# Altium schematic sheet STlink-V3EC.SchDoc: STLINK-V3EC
size A3; Date: Not used; ApprovedBy: Not used; CheckedBy: Not used; Author: Not used; CompanyName: STMicroelectronics; DrawnBy: Not used; Engineer: Not used; Organization: Not used; Address1: Not used; Address2: Not used; Address3: Not used; Address4: Not used; DocumentNumber: Not used; Revision: Not used; SheetNumber: 6; SheetTotal: 7
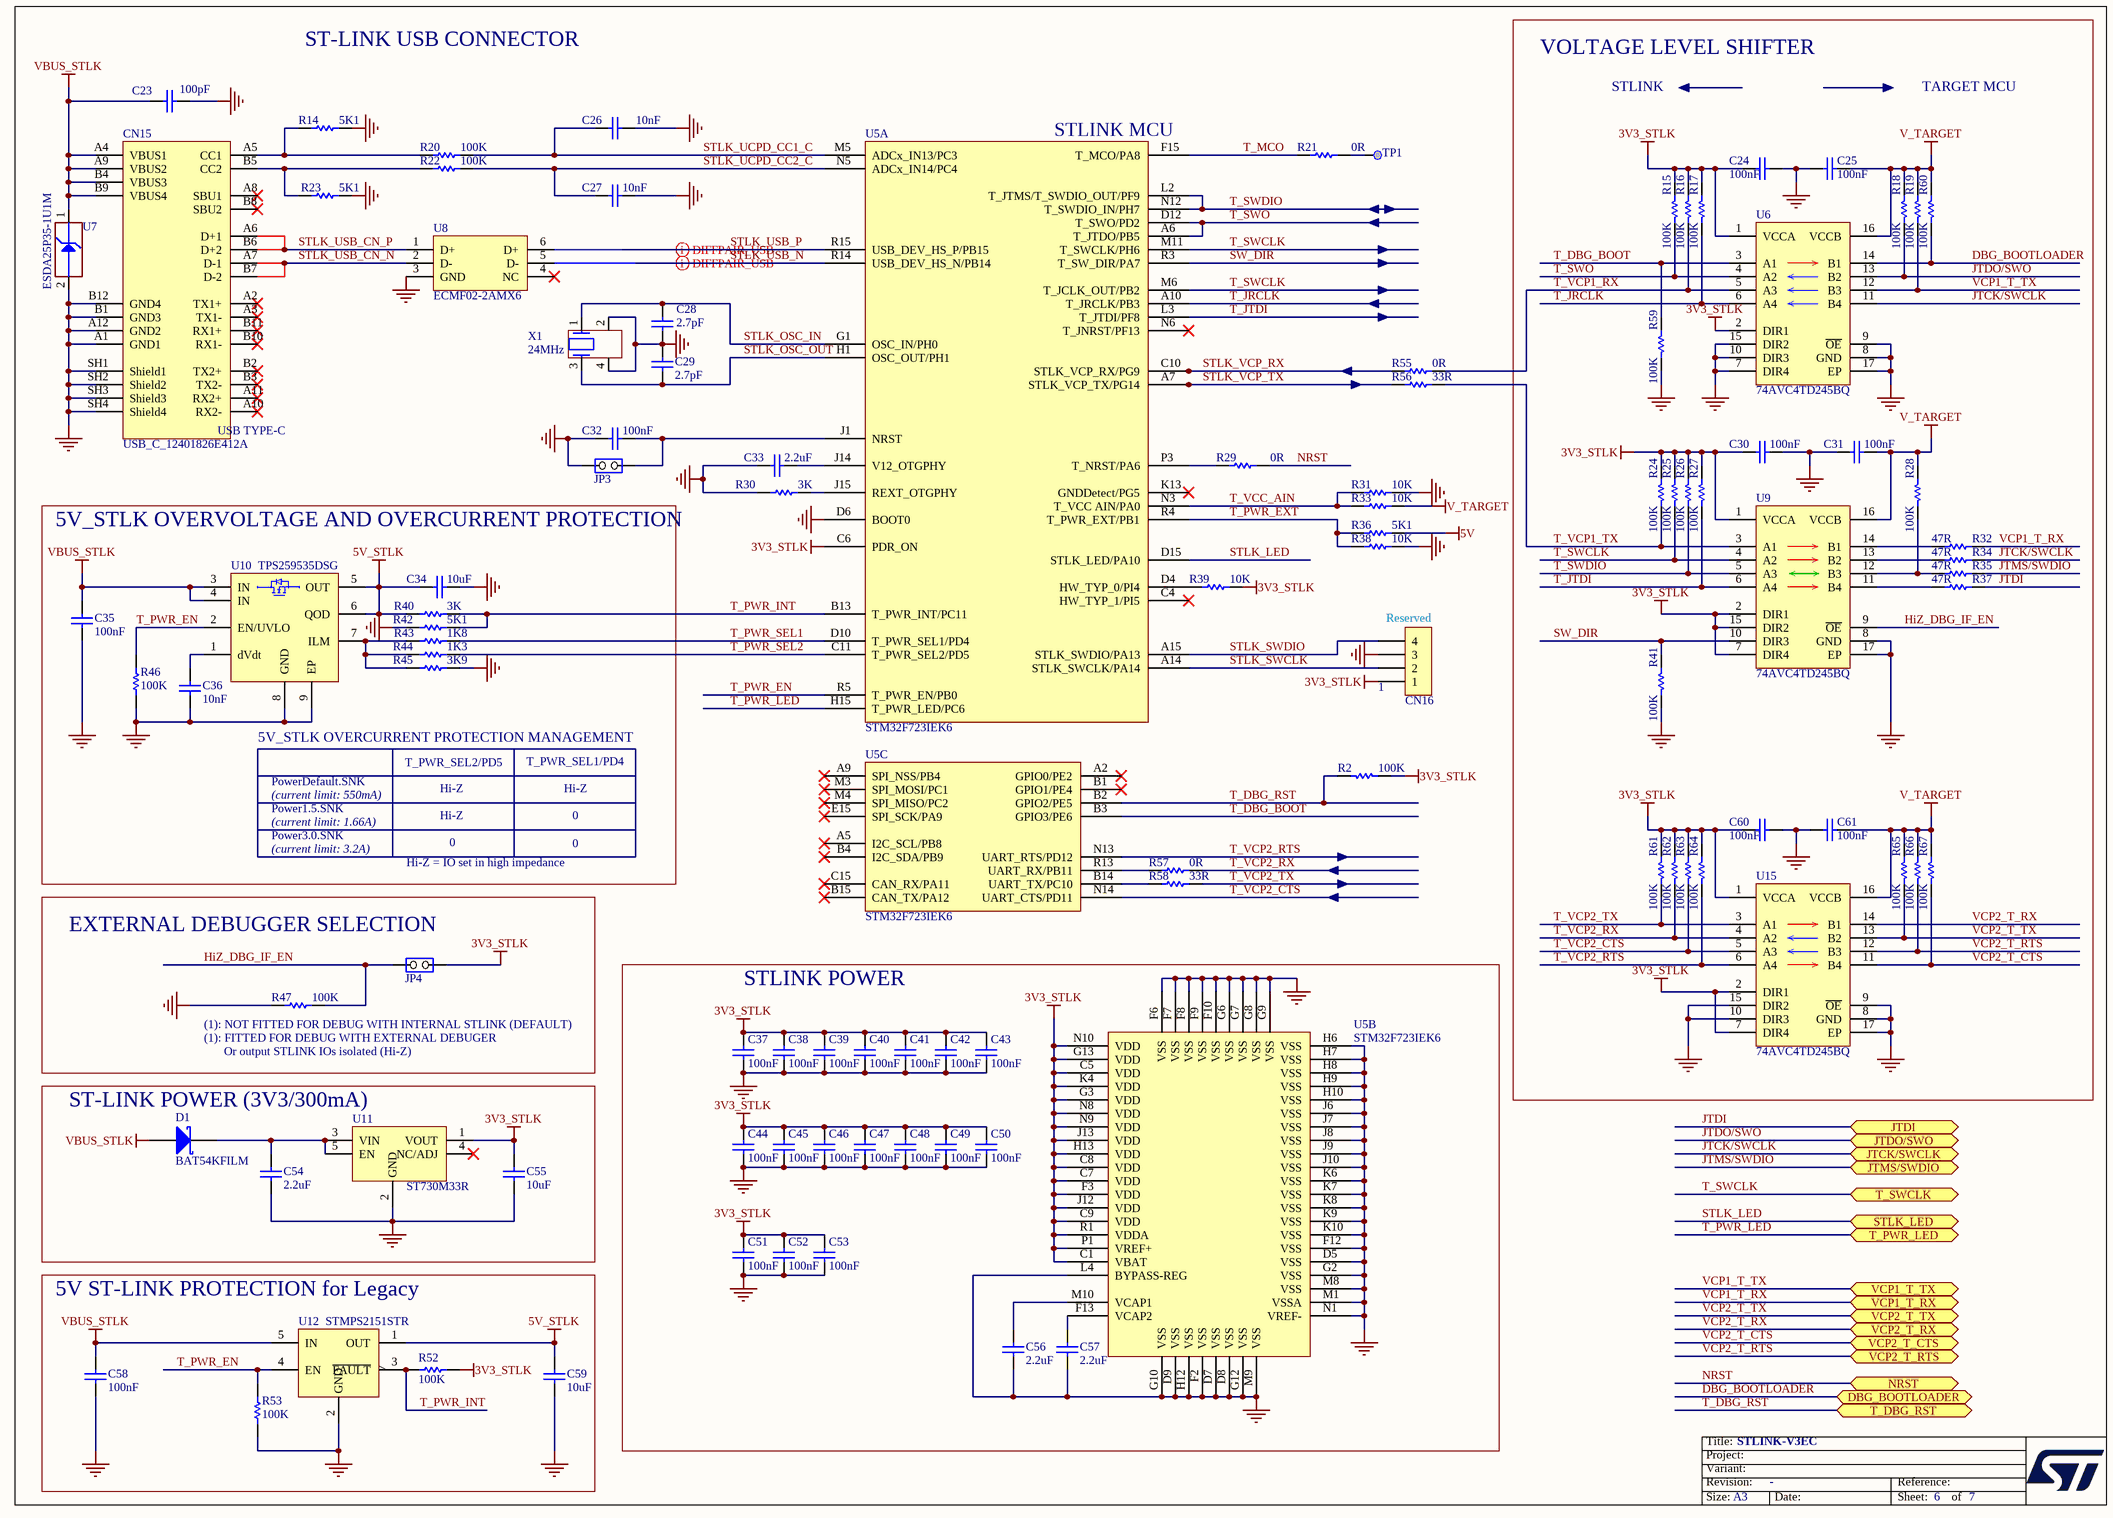
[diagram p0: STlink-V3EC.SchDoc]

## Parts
C23  value 100pF  [C0402]  (hidden comment: Capacitor)
C24  value 100nF  [C0402]  (hidden comment: Capacitor)
C25  value 100nF  [C0402]  (hidden comment: Capacitor)
C26  value 10nF  [C0402]  (hidden comment: Capacitor)
C27  value 10nF  [C0402]  (hidden comment: Capacitor)
C28  value 2.7pF  [C0402]  (hidden comment: Capacitor)
C29  value 2.7pF  [C0402]  (hidden comment: Capacitor)
C30  value 100nF  [C0402]  (hidden comment: Capacitor)
C31  value 100nF  [C0402]  (hidden comment: Capacitor)
C32  value 100nF  [C0402]  (hidden comment: Capacitor)
C33  value 2.2uF  [C0402]  (hidden comment: Capacitor)
C34  value 10uF  [C0603]  (hidden comment: Capacitor)
C35  value 100nF  [C0402]  (hidden comment: Capacitor)
C36  value 10nF  [C0402]  (hidden comment: Capacitor)
C37  value 100nF  [C0402]  (hidden comment: Capacitor)
C38  value 100nF  [C0402]  (hidden comment: Capacitor)
C39  value 100nF  [C0402]  (hidden comment: Capacitor)
C40  value 100nF  [C0402]  (hidden comment: Capacitor)
C41  value 100nF  [C0402]  (hidden comment: Capacitor)
C42  value 100nF  [C0402]  (hidden comment: Capacitor)
C43  value 100nF  [C0402]  (hidden comment: Capacitor)
C44  value 100nF  [C0402]  (hidden comment: Capacitor)
C45  value 100nF  [C0402]  (hidden comment: Capacitor)
C46  value 100nF  [C0402]  (hidden comment: Capacitor)
C47  value 100nF  [C0402]  (hidden comment: Capacitor)
C48  value 100nF  [C0402]  (hidden comment: Capacitor)
C49  value 100nF  [C0402]  (hidden comment: Capacitor)
C50  value 100nF  [C0402]  (hidden comment: Capacitor)
C51  value 100nF  [C0402]  (hidden comment: Capacitor)
C52  value 100nF  [C0402]  (hidden comment: Capacitor)
C53  value 100nF  [C0402]  (hidden comment: Capacitor)
C54  value 2.2uF  [C0805]  (hidden comment: Capacitor)
C55  value 10uF  [C0603]  (hidden comment: Capacitor)
C56  value 2.2uF  [C0402]  (hidden comment: Capacitor)
C57  value 2.2uF  [C0402]  (hidden comment: Capacitor)
C58  value 100nF  [C0402]  (hidden comment: Capacitor)
C59  value 10uF  [C0603]  (hidden comment: Capacitor)
C60  value 100nF  [C0402]  (hidden comment: Capacitor)
C61  value 100nF  [C0402]  (hidden comment: Capacitor)
CN15  value USB_C_12401826E412A  [CON_USB-TYPEC_AMPHENOL_12401826E412A]  (hidden comment: USB_TYPE_C_Receptacle)
CN16  Header 4x1  [CON_SAMTEC_TSW-104-07-G-S]  (value not drawn)
D1  value BAT54KFILM  [DIO_SOD523_1A_2K]  (hidden comment: SCHOTTKY_1A_2K)
JP3  Jumper_Header 2x1  [CON_SAMTEC_TSW-102-07-G-S]  (value not drawn)
JP4  Jumper_Header 2x1  [CON_SAMTEC_TSW-102-07-G-S]  (value not drawn)
R2  value 100K  [R0402]  (hidden comment: Resistor)
R14  value 5K1  [R0402]  (hidden comment: Resistor)
R15  value 100K  [R0402]  (hidden comment: Resistor)
R16  value 100K  [R0402]  (hidden comment: Resistor)
R17  value 100K  [R0402]  (hidden comment: Resistor)
R18  value 100K  [R0402]  (hidden comment: Resistor)
R19  value 100K  [R0402]  (hidden comment: Resistor)
R20  value 100K  [R0402]  (hidden comment: Resistor)
R21  value 0R  [R0402]  (hidden comment: Resistor)
R22  value 100K  [R0402]  (hidden comment: Resistor)
R23  value 5K1  [R0402]  (hidden comment: Resistor)
R24  value 100K  [R0402]  (hidden comment: Resistor)
R25  value 100K  [R0402]  (hidden comment: Resistor)
R26  value 100K  [R0402]  (hidden comment: Resistor)
R27  value 100K  [R0402]  (hidden comment: Resistor)
R28  value 100K  [R0402]  (hidden comment: Resistor)
R29  value 0R  [R0402]  (hidden comment: Resistor)
R30  value 3K  [R0402]  (hidden comment: Resistor)
R31  value 10K  [R0402]  (hidden comment: Resistor)
R32  value 47R  [R0402]  (hidden comment: Resistor)
R33  value 10K  [R0402]  (hidden comment: Resistor)
R34  value 47R  [R0402]  (hidden comment: Resistor)
R35  value 47R  [R0402]  (hidden comment: Resistor)
R36  value 5K1  [R0402]  (hidden comment: Resistor)
R37  value 47R  [R0402]  (hidden comment: Resistor)
R38  value 10K  [R0402]  (hidden comment: Resistor)
R39  value 10K  [R0402]  (hidden comment: Resistor)
R40  value 3K  [R0402]  (hidden comment: Resistor)
R41  value 100K  [R0402]  (hidden comment: Resistor)
R42  value 5K1  [R0402]  (hidden comment: Resistor)
R43  value 1K8  [R0402]  (hidden comment: Resistor)
R44  value 1K3  [R0402]  (hidden comment: Resistor)
R45  value 3K9  [R0402]  (hidden comment: Resistor)
R46  value 100K  [R0402]  (hidden comment: Resistor)
R47  value 100K  [R0402]  (hidden comment: Resistor)
R52  value 100K  [R0402]  (hidden comment: Resistor)
R53  value 100K  [R0402]  (hidden comment: Resistor)
R55  value 0R  [R0402]  (hidden comment: Resistor)
R56  value 33R  [R0402]  (hidden comment: Resistor)
R57  value 0R  [R0402]  (hidden comment: Resistor)
R58  value 33R  [R0402]  (hidden comment: Resistor)
R59  value 100K  [R0402]  (hidden comment: Resistor)
R60  value 100K  [R0402]  (hidden comment: Resistor)
R61  value 100K  [R0402]  (hidden comment: Resistor)
R62  value 100K  [R0402]  (hidden comment: Resistor)
R63  value 100K  [R0402]  (hidden comment: Resistor)
R64  value 100K  [R0402]  (hidden comment: Resistor)
R65  value 100K  [R0402]  (hidden comment: Resistor)
R66  value 100K  [R0402]  (hidden comment: Resistor)
R67  value 100K  [R0402]  (hidden comment: Resistor)
TP1  Test Point  [TP_SMD_1MM]  (value not drawn)  (no BOM)
U5  value STM32F723IEK6  [ICC_UFBGA201_176+25_10X10_P065]  (hidden comment: STLINK-V3EC_Old)  (parts A,B,C of 3)
U6  74AVC4TD245BQ  [ICC_DHVQFN16-EPAD_SOT763-1_2P5X3P5_H0P85_P050]
U7  value ESDA25P35-1U1M  [ESD_QFN1610_2N_1K_2A]  (hidden comment: ESD-TRANSIL)
U8  ECMF02-2AMX6  [ESD_QFN-6L_1P7X1P5_P050]
U9  74AVC4TD245BQ  [ICC_DHVQFN16-EPAD_SOT763-1_2P5X3P5_H0P85_P050]
U10  TPS259535DSG  [ICC_WSON8-EPAD_2X2_P050]
U11  ST730M33R  [ICC_SOT23-5L_H1P45]
U12  STMPS2151STR  [MOS_SOT23-5L]
U15  74AVC4TD245BQ  [ICC_DHVQFN16-EPAD_SOT763-1_2P5X3P5_H0P85_P050]
X1  value 24MHz  [CRY_NX2016SA_4P]  (hidden comment: XTAL_4_PINS)

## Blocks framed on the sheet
VOLTAGE LEVEL SHIFTER: C24 C25 C30 C31 C60 C61 R15-R19 R24-R28 R32 R34 R35 R37 R41 R59-R67 U6 U9 U15
5V_STLK OVERVOLTAGE AND OVERCURRENT PROTECTION: C34-C36 R40 R42-R46 U10
EXTERNAL DEBUGGER SELECTION: JP4 R47
STLINK POWER: C37-C53 C56 C57 U5
ST-LINK POWER (3V3/300mA): C54 C55 D1 U11
5V ST-LINK PROTECTION for Legacy: C58 C59 R52 R53 U12

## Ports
DBG_BOOTLOADER (bidir), JTCK/SWCLK (bidir), JTDI (bidir), JTDO/SWO (bidir), JTMS/SWDIO (bidir), NRST (bidir), STLK_LED (bidir), T_DBG_RST (bidir), T_PWR_LED (bidir), T_SWCLK (bidir), VCP1_T_RX (bidir), VCP1_T_TX (bidir), VCP2_T_CTS (bidir), VCP2_T_RTS (bidir), VCP2_T_RX (bidir), VCP2_T_TX (bidir)

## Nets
3V3_STLK: C24.2 C30.2 C37.1 C38.1 C39.1 C40.1 C41.1 C42.1 C43.1 C44.1 C45.1 C46.1 C47.1 C48.1 C49.1 C50.1 C51.1 C52.1 C53.1 C55.2 C60.2 CN16.1 JP4.1(COMMON) R2.1 R15.2 R16.2 R17.2 R24.1 R25.2 R26.2 R27.2 R39.2 R52.1 R61.2 R62.2 R63.2 R64.2 U5.C1(VBAT) U5.C5(VDD) U5.C6(PDR_ON) U5.C7(VDD) U5.C8(VDD) U5.C9(VDD) U5.F3(VDD) U5.G3(VDD) U5.G13(VDD) U5.H13(VDD) U5.J12(VDD) U5.J13(VDD) U5.K4(VDD) U5.N8(VDD) U5.N9(VDD) U5.N10(VDD) U5.P1(VREF+) U5.R1(VDDA) U6.1(VCCA) U6.2(DIR1) U9.1(VCCA) U9.2(DIR1) U9.7(DIR4) U9.15(DIR2) U11.1(VOUT) U15.1(VCCA) U15.2(DIR1) U15.7(DIR4)
5V: R36.2
5V_STLK: C34.2 C59.2 R40.1 U10.5(OUT) U10.6(QOD) U12.1(OUT)
GND: C23.2 C24.1 C25.2 C26.2 C27.2 C28.1 C29.2 C30.1 C31.2 C32.1 C33.1 C34.1 C35.1 C36.1 C37.2 C38.2 C39.2 C40.2 C41.2 C42.2 C43.2 C44.2 C45.2 C46.2 C47.2 C48.2 C49.2 C50.2 C51.2 C52.2 C53.2 C54.1 C55.1 C56.1 C57.1 C58.1 C59.1 C60.1 C61.2 CN15.A1(GND1) CN15.A12(GND2) CN15.B1(GND3) CN15.B12(GND4) CN15.SH1(Shield1) CN15.SH2(Shield2) CN15.SH3(Shield3) CN15.SH4(Shield4) CN16.3 JP3.2(NO) R14.2 R23.2 R30.2 R31.2 R38.2 R41.1 R42.1 R45.2 R46.1 R47.1 R53.1 R59.1 U5.D5(VSS) U5.D6(BOOT0) U5.D7(VSS) U5.D8(VSS) U5.D9(VSS) U5.F2(VSS) U5.F6(VSS) U5.F7(VSS) U5.F8(VSS) U5.F9(VSS) U5.F10(VSS) U5.F12(VSS) U5.G2(VSS) U5.G6(VSS) U5.G7(VSS) U5.G8(VSS) U5.G9(VSS) U5.G10(VSS) U5.G12(VSS) U5.H6(VSS) U5.H7(VSS) U5.H8(VSS) U5.H9(VSS) U5.H10(VSS) U5.H12(VSS) U5.J6(VSS) U5.J7(VSS) U5.J8(VSS) U5.J9(VSS) U5.J10(VSS) U5.K6(VSS) U5.K7(VSS) U5.K8(VSS) U5.K9(VSS) U5.K10(VSS) U5.L4(BYPASS-REG) U5.M1(VSSA) U5.M8(VSS) U5.M9(VSS) U5.N1(VREF-) U6.7(DIR4) U6.8(GND) U6.9(~{OE}) U6.10(DIR3) U6.15(DIR2) U6.17(EP) U7.2(GND) U8.3(GND) U9.8(GND) U9.17(EP) U10.8(GND) U10.9(EP) U11.2(GND) U12.2(GND) U15.8(GND) U15.9(~{OE}) U15.10(DIR3) U15.15(DIR2) U15.17(EP) X1.2 X1.4
V_TARGET: C25.1 C31.1 C61.1 R18.2 R19.2 R28.2 R33.2 R60.2 R65.2 R66.2 R67.2 U6.16(VCCB) U9.16(VCCB) U15.16(VCCB)
VBUS_STLK: C23.1 C35.2 C58.2 CN15.A4(VBUS1) CN15.A9(VBUS2) CN15.B4(VBUS3) CN15.B9(VBUS4) D1.1(A) U7.1(IO1) U10.3(IN) U10.4(IN) U12.5(IN)
DBG_BOOTLOADER: R60.1 U6.14(B1) ; port DBG_BOOTLOADER
HiZ_DBG_IF_EN: JP4.2(NO) R47.2 U9.9(~{OE})
JTCK/SWCLK: R34.2 U6.11(B4) ; port JTCK/SWCLK
JTDI: R37.2 ; port JTDI
JTDO/SWO: R18.1 U6.13(B2) ; port JTDO/SWO
JTMS/SWDIO: R35.2 ; port JTMS/SWDIO
NRST: R29.2 ; port NRST
STLK_LED: U5.D15(STLK_LED/PA10) ; port STLK_LED
STLK_OSC_IN: C28.2 U5.G1(OSC_IN/PH0) X1.1
STLK_OSC_OUT: C29.1 U5.H1(OSC_OUT/PH1) X1.3
STLK_SWCLK: CN16.2 U5.A14(STLK_SWCLK/PA14)
STLK_SWDIO: CN16.4 U5.A15(STLK_SWDIO/PA13)
STLK_UCPD_CC1_C: C26.1 R20.2 U5.M5(ADCx_IN13/PC3)
STLK_UCPD_CC2_C: C27.1 R22.2 U5.N5(ADCx_IN14/PC4)
STLK_USB_CN_N: CN15.A7(D-1) CN15.B7(D-2) U8.2(D-)
STLK_USB_CN_P: CN15.A6(D+1) CN15.B6(D+2) U8.1(D+)
STLK_USB_N: U5.R14(USB_DEV_HS_N/PB14) U8.5(D-)
STLK_USB_P: U5.R15(USB_DEV_HS_P/PB15) U8.6(D+)
STLK_VCP_RX: R55.1 U5.C10(STLK_VCP_RX/PG9)
STLK_VCP_TX: R56.1 U5.A7(STLK_VCP_TX/PG14)
SW_DIR: R41.2 U5.R3(T_SW_DIR/PA7) U9.10(DIR3)
T_DBG_BOOT: R59.2 U5.B3(GPIO3/PE6) U6.3(A1)
T_DBG_RST: R2.2 U5.B2(GPIO2/PE5) ; port T_DBG_RST
T_JRCLK: R17.1 U5.A10(T_JRCLK/PB3) U6.6(A4)
T_JTDI: R27.1 U5.L3(T_JTDI/PF8) U9.6(A4)
T_MCO: R21.1 U5.F15(T_MCO/PA8)
T_PWR_EN: R46.2 R53.2 U5.R5(T_PWR_EN/PB0) U10.2(EN/UVLO) U12.4(EN)
T_PWR_EXT: R36.1 R38.1 U5.R4(T_PWR_EXT/PB1)
T_PWR_INT: R40.2 R42.2 R52.2 U5.B13(T_PWR_INT/PC11) U12.3(~{FAULT})
T_PWR_LED: U5.H15(T_PWR_LED/PC6) ; port T_PWR_LED
T_PWR_SEL1: R43.2 U5.D10(T_PWR_SEL1/PD4)
T_PWR_SEL2: R44.2 U5.C11(T_PWR_SEL2/PD5)
T_SWCLK: R25.1 U5.M6(T_JCLK_OUT/PB2) U5.M11(T_SWCLK/PH6) U9.4(A2) ; port T_SWCLK
T_SWDIO: R26.1 U5.L2(T_JTMS/T_SWDIO_OUT/PF9) U5.N12(T_SWDIO_IN/PH7) U9.5(A3)
T_SWO: R15.1 U5.A6(T_JTDO/PB5) U5.D12(T_SWO/PD2) U6.4(A2)
T_VCC_AIN: R31.1 R33.1 U5.N3(T_VCC_AIN/PA0)
T_VCP1_RX: R16.1 R55.2 U6.5(A3)
T_VCP1_TX: R24.2 R56.2 U9.3(A1)
T_VCP2_CTS: R63.1 U5.N14(UART_CTS/PD11) U15.5(A3)
T_VCP2_RTS: R64.1 U5.N13(UART_RTS/PD12) U15.6(A4)
T_VCP2_RX: R57.2 R62.1 U15.4(A2)
T_VCP2_TX: R58.2 R61.1 U15.3(A1)
VCP1_T_RX: R32.2 ; port VCP1_T_RX
VCP1_T_TX: R19.1 U6.12(B3) ; port VCP1_T_TX
VCP2_T_CTS: R67.1 U15.11(B4) ; port VCP2_T_CTS
VCP2_T_RTS: R66.1 U15.12(B3) ; port VCP2_T_RTS
VCP2_T_RX: U15.14(B1) ; port VCP2_T_RX
VCP2_T_TX: R65.1 U15.13(B2) ; port VCP2_T_TX
NetC32_2: C32.2 JP3.1(COMMON) U5.J1(NRST)
NetC33_2: C33.2 U5.J14(V12_OTGPHY)
NetC36_2: C36.2 U10.1(dVdt)
NetC54_2: C54.2 D1.2(K) U11.3(VIN) U11.5(EN)
NetC56_2: C56.2 U5.M10(VCAP1)
NetC57_2: C57.2 U5.F13(VCAP2)
NetCN15_A5: CN15.A5(CC1) R14.1 R20.1
NetCN15_B5: CN15.B5(CC2) R22.1 R23.1
NetR21_2: R21.2 TP1.1
NetR28_1: R28.1 R35.1 U9.12(B3)
NetR29_1: R29.1 U5.P3(T_NRST/PA6)
NetR30_1: R30.1 U5.J15(REXT_OTGPHY)
NetR32_1: R32.1 U9.14(B1)
NetR34_1: R34.1 U9.13(B2)
NetR37_1: R37.1 U9.11(B4)
NetR39_1: R39.1 U5.D4(HW_TYP_0/PI4)
NetR43_1: R43.1 R44.1 R45.1 U10.7(ILM)
NetR57_1: R57.1 U5.R13(UART_RX/PB11)
NetR58_1: R58.1 U5.B14(UART_TX/PC10)

Not connected (* = marked no-connect by the designer): CN15 A2(TX1+)* A3(TX1-)* A8(SBU1)* A10(RX2-)* A11(RX2+)* B2(TX2+)* B3(TX2-)* B8(SBU2)* B10(RX1-)* B11(RX1+)*; U5 A2(GPIO0/PE2)* A5(I2C_SCL/PB8)* A9(SPI_NSS/PB4)* B1(GPIO1/PE4)* B4(I2C_SDA/PB9)* B15(CAN_TX/PA12)* C4(HW_TYP_1/PI5)* C15(CAN_RX/PA11)* E15(SPI_SCK/PA9)* K13(GNDDetect/PG5)* M3(SPI_MOSI/PC1)* M4(SPI_MISO/PC2)* N6(T_JNRST/PF13)*; U8 4(NC)*; U11 4(NC/ADJ)*

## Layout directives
differential pair; rule Impedance Constraint [Min = 85.00    Max = 95.00    ]: STLK_USB_N, STLK_USB_P

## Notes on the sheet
- ST-LINK USB CONNECTOR
- STLINK
- TARGET MCU
- (near U5) STLINK MCU
- (near CN16) Reserved
- (near CN16) 1
- 5V_STLK OVERCURRENT PROTECTION MANAGEMENT
- PowerDefault.SNK
- T_PWR_SEL2/PD5
- T_PWR_SEL1/PD4
- (current limit: 550mA)
- (current limit: 1.66A)
- (current limit: 3.2A)
- Power1.5.SNK
- Power3.0.SNK
- Hi-Z
- 0
- Hi-Z = IO set in high impedance
- (near R47) (1): NOT FITTED FOR DEBUG WITH INTERNAL STLINK (DEFAULT)
- (near R47) (1): FITTED FOR DEBUG WITH EXTERNAL DEBUGER
- (near R47) Or output STLINK IOs isolated (Hi-Z)

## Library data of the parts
C23 = MCD-00205: Capacitor, MLCC, 100pF, 50V, NPO, +/-5%, 0402, T=0.5mm; Part_Preference: Recommended; Manufacturer: YAGEO; Manufacturer_Part_Number: CC0402JRNPO9BN101; Component_Country_Of_Origin: China
C24 C25 C30-C32 C37-C53 C60 C61 = MCD-00006: Capacitor, MLCC, 100nF, 16V, X7R, 10%, 0402, T=0.5mm; Manufacturer_Part_Number: CC0402KRX7R7BB104; Manufacturer: YAGEO; Alternate_Manufacturer_Part_Number: GCM155R71C104KA55D; Alternate_Manufacturer: MURATA; Provided_By: SUBCO
C26 C27 C36 = MCD-02198: Capacitor, MLCC, 10nF, 50V, X7R, +/-10%, 0402, T=0.5mm; Part_Preference: Recommended; Manufacturer: YAGEO; Manufacturer_Part_Number: CC0402KRX7R9BB103; Order_Code_RS: 6169644; Component_Country_Of_Origin: China
C28 C29 = MCD-01774: Capacitor, MLCC, 2.7pF, 50V, NPO, +/-0.1pF, 0402, T=0.5mm; Part_Preference: Recommended; Manufacturer: YAGEO; Manufacturer_Part_Number: CC0402BRNPO9BN2R7; Component_Country_Of_Origin: China
C33 C56 C57 = MCD-02606: Capacitor, MLCC, 2.2uF, 6.3V, X5R, +/-10%, 0402, T=0.5mm; Part_Preference: Recommended; Manufacturer: YAGEO; Manufacturer_Part_Number: CC0402KRX5R5BB225; Order_Code_RS: 1992205
C34 C55 = MCD-00099: Capacitor, MLCC, 10uF, 10V, X5R, +/-10%, 0603, T=0.8mm; Part_Preference: Recommended; Manufacturer: MURATA; Manufacturer_Part_Number: GRM188R61A106KE69D; Order_Code_RS: 170-6168; Component_Country_Of_Origin: Japan
C35 = MCD-02355: Capacitor, MLCC, 100nF, 25V, X7R, +/-10%, 0402, T=0.5mm; Part_Preference: Recommended; Manufacturer: WALSIN; Manufacturer_Part_Number: 0402B104K250CT; Order_Code_RS: 176-3114; Component_Country_Of_Origin: Unknown
C54 = MCD-02372: Capacitor, MLCC, 2.2uF, 25V, X7R, +/-10%, 0805, T=1,25mm; Manufacturer_Part_Number: GRM21BR71E225KE11L; Manufacturer: MURATA; Part_Preference: Recommended; ECCN_US: EAR99; ECCN_EU: NEC; Provided_By: SUBCO
C58 = MCD-02355: Capacitor, MLCC, 100nF, 25V, X7R, +/-10%, 0402, T=0.5mm; Part_Preference: Recommended; Manufacturer: WALSIN; Manufacturer_Part_Number: 0402B104K250CT; Order_Code_RS: 176-3114; Component_Country_Of_Origin: Unknown; ShowFields: YES; ID: 4461
C59 = MCD-00099: Capacitor, MLCC, 10uF, 10V, X5R, +/-10%, 0603, T=0.8mm; Part_Preference: Recommended; Manufacturer: MURATA; Manufacturer_Part_Number: GRM188R61A106KE69D; Order_Code_RS: 170-6168; Component_Country_Of_Origin: Japan; ShowFields: YES; ID: 2770
CN15 = MCD-03232: USB_TypeC, 24 pins, RA, SMD, T=2.96mm; Part_Type: Connector; Part_Preference: Recommended; Manufacturer: AMPHENOL ICC; Manufacturer_Part_Number: 12401826E412A; Component_Country_Of_Origin: China°; ShowFields: YES; ID: 5348
CN16 = MCD-00029: Header, 4x1, 2,54mm, VR, TH, Height 5.84mm/2.54mm; Manufacturer_Part_Number: TSW-104-07-x-S; Manufacturer: SAMTEC; Part_Type: Connector; Provided_By: SUBCO
D1 = MCD-01677: Small signal Schottky diodes; BMS_Part_Number: 9151123; Part_Type: Diode; Part_Preference: Recommended; Manufacturer: STMICROELECTRONICS; Manufacturer_HQ_COO: EU; Component_Country_Of_Origin: China; ShowFields: YES; ID: 3777
JP3 JP4 = MCD-00045: Header, 2x1, 2,54mm, VR, TH, Height 5.84mm/2.54mm; Part_Preference: Recommended; Part_Type: Connector; Manufacturer: SAMTEC; Manufacturer_Part_Number: TSW-102-07-G-S; Alternate_Manufacturer: JIUBABA; LIANYI; Alternate_Manufacturer_Part_Number: 313102S111116;313102S111116
R2 R15-R19 R24-R28 R41 R59-R67 = MCD-00059: Resistor,100K,0402,1%,1/16W; Manufacturer_Part_Number: RC0402FR-07100KL; Manufacturer: YAGEO; Alternate_Manufacturer_Part_Number: RT0402FRE07100KL; Provided_By: Subcon; Initial_Board_Reference: MB1274
R14 R23 R36 R42 = MCD-00333: Resistor, 5K1, 0402, +/-1%, 1/16W; Part_Preference: Recommended; Manufacturer: YAGEO; Manufacturer_Part_Number: RC0402FR-075K1L
R20 R22 R46 R47 R52 R53 = MCD-00059: Resistor, 100K, 0402, +/-1%, 1/16W; Part_Preference: Recommended; Manufacturer: YAGEO; Manufacturer_Part_Number: RC0402FR-07100KL; Component_Country_Of_Origin: China; ShowFields: YES; ID: 2533
R21 R29 R55 R57 = MCD-00052: Resistor, 0R, 0402, +/-5%, 1/16W; Part_Preference: Recommended; Manufacturer: YAGEO; Manufacturer_Part_Number: RC0402JR-070RL; Order_Code_RS: 618-5804; Component_Country_Of_Origin: China
R30 = MCD-00185: Resistor,3K,0402,1%,1/16W; Manufacturer_Part_Number: RC0402FR-073KL; Manufacturer: YAGEO; Provided_By: SUBCO
R31 R33 R38 R39 = MCD-00053: Resistor,10K,0402,1%,1/16W; Manufacturer_Part_Number: RC0402FR-0710KL; Manufacturer: YAGEO; Provided_By: SUBCO
R32 R34 R35 R37 = MCD-00481: Resistor,47R,0402,1%,1/16W; Manufacturer_Part_Number: RC0402FR-0747RL; Manufacturer: YAGEO; Provided_By: SUBCO; Initial_Board_Reference: MBxxxx
R40 = MCD-00185: Resistor, 3K, 0402, +/-1%, 1/16W; Part_Preference: Recommended; Manufacturer: YAGEO; Manufacturer_Part_Number: RC0402FR-073KL; Component_Country_Of_Origin: China
R43 = MCD-00409: Resistor, 1K8, 0402, +/-1%, 1/16W; Part_Preference: Recommended; Manufacturer: YAGEO; Manufacturer_Part_Number: RC0402FR-071K8L; Component_Country_Of_Origin: China
R44 = MCD-00381: Resistor, 1K3, 0402, +/-1%, 1/16W; Part_Preference: Recommended; Manufacturer: YAGEO; Manufacturer_Part_Number: RC0402FR-071K3L; Component_Country_Of_Origin: China; ShowFields: YES; ID: 2898
R45 = MCD-02455: Resistor, 3K9, 0402, +/-1%, 1/16W, +/-100ppm/°C; Part_Preference: Recommended; Manufacturer: YAGEO; Manufacturer_Part_Number: RC0402FR-073K9L; Order_Code_RS: 198-7783; Component_Country_Of_Origin: China; ShowFields: YES; ID: 4561
R56 R58 = MCD-00455: Resistor, 33R, 0402, +/-1%, 1/16W; Part_Preference: Recommended; Manufacturer: YAGEO; Manufacturer_Part_Number: RC0402FR-0733RL; Component_Country_Of_Origin: China; ShowFields: YES; ID: 2821
TP1 = MCD-00074: Test Point 1mm; Part_Type: Mechanical
U5 = MCD-02706: MCU, ARM Cortex-M7 32-bit, 512KB Flash, 276KB RAM, With Crypto; BMS_Part_Number: 9175300; Part_Type: IC; Part_Preference: Not recommended; Manufacturer: STMICROELECTRONICS; Order_Code_RS: 135-8241; ShowFields: YES; ID: 4812
U6 U9 U15 = MCD-01945: 4-bit dual supply translating transceiver with configurable voltage translation; 3-state; Part_Type: IC; Manufacturer_Part_Number: 74AVC4TD245BQ,115; Manufacturer: NEXPERIA; Part_Preference: Recommended
U7 = MCD-01207: High power Transient voltage suppressor:25V/35A EOS and ESD transients protection.; Part_Type: Diode; Manufacturer: STMICROELECTRONICS; BMS_Part_Number: 9179045; ECCN_US: EAR99; ECCN_EU: NEC; Provided_By: SUBCO with ST control
U8 = MCD-00649: Common mode filter with ESD protection for USB 2.0 interface; BMS_Part_Number: 9151138; Part_Type: Diode; Part_Preference: Recommended; Manufacturer: STMICROELECTRONICS; Manufacturer_HQ_COO: EU; Component_Country_Of_Origin: China; ShowFields: YES; ID: 3094
U10 = MCD-02532: IC, 2V7 to 18V, 4A, 34mR, eFuse with fast overvoltage protection; Part_Preference: Recommended; Manufacturer: TEXAS INSTRUMENTS; Component_Country_Of_Origin: Thailand; ShowFields: YES; ID: 4638
U11 = MCD-02514: LDO, 3.3V, 300mA, High input voltage: 2.5V to 28V, SOT23-5L; Part_Type: IC; Part_Preference: Recommended; Manufacturer: STMICROELECTRONICS
U12 = MCD-00159: 500mA, Enhanced single channel power switches with active high enable pin; BMS_Part_Number: 9159009; Part_Type: IC; Part_Preference: Recommended; Manufacturer: STMICROELECTRONICS; Manufacturer_HQ_COO: EU; Component_Country_Of_Origin: Malaysia; ShowFields: YES; ID: 2708
X1 = MCD-01036: Crystal, 24MHz, 6pF, +/-20ppm, 80R, 2x1.6mm; BMS_Part_Number: 9157045; Part_Type: Crystal_Osc; Part_Preference: Recommended; Manufacturer: NDK; Manufacturer_Part_Number: NX2016SA-24MHZ-EXS00A-CS10820; Component_Country_Of_Origin: Unknown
